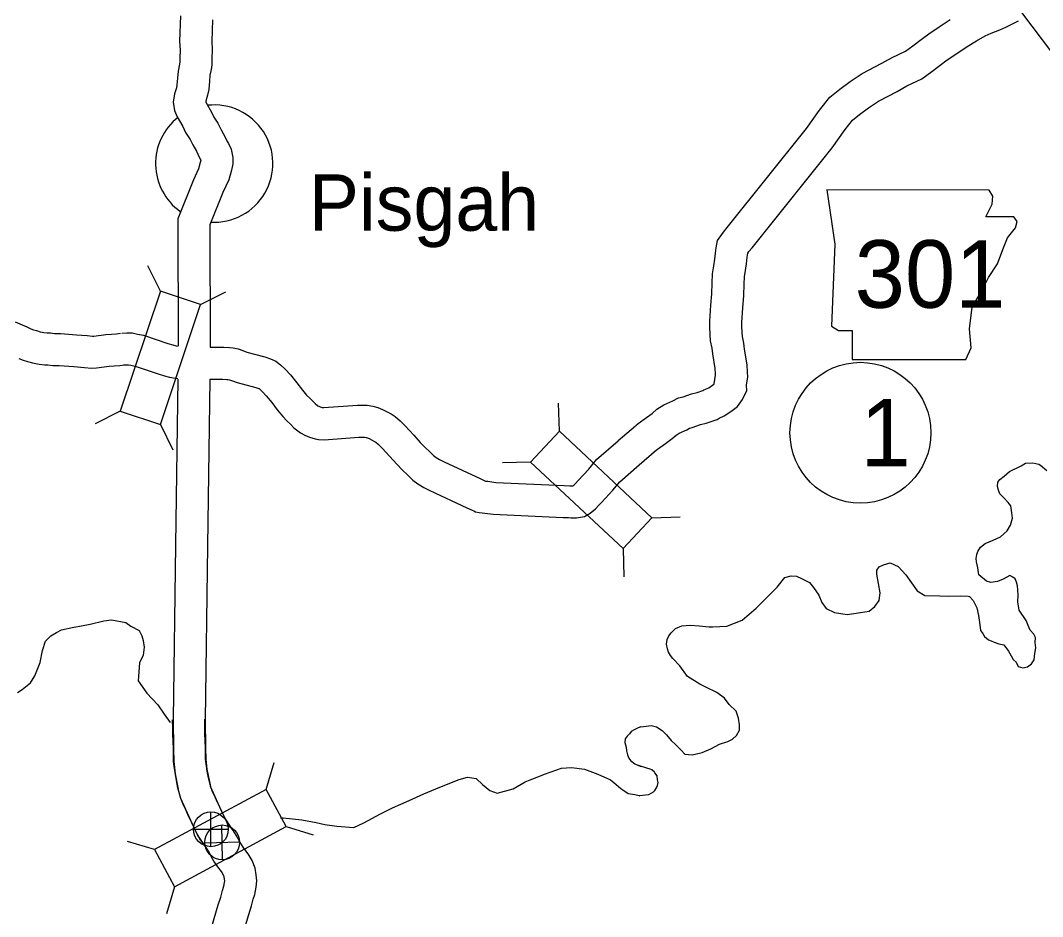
# Model space of a CAD drawing. Extents: x 79818 to 83933, y 50884 to 53307.
# Drawn here: x 81261.3 to 81389, y 52890.4 to 53002.4 of the extents above; entities that cross this region are included whole.
import ezdxf

# ---------------------------------------------------------------- set-up
doc = ezdxf.new("R2010")
doc.units = 0
for name, color, linetype in [('Level 10', 7, 'Continuous'), ('Level 2', 7, 'Continuous'), ('Level 20', 7, 'Continuous'), ('Level 21', 7, 'Continuous'), ('Level 24', 7, 'Continuous'), ('Level 26', 7, 'Continuous'), ('Level 27', 7, 'Continuous')]:
    doc.layers.add(name, color=color, linetype=linetype)

msp = doc.modelspace()

# ---------------------------------------------------------------- linework, layer by layer
at = {"layer": 'Level 10'}
for p, q in [((81280.69, 52936.77), (81280.4, 52915.03)), ((81284.69, 52936.72), (81284.4, 52914.97))]:
    msp.add_line(p, q, dxfattribs=at)
for points in [[(81281.3, 53002.94), (81281.19, 52999.77), (81281.24, 52998.67), (81281.22, 52997.72), (81281.21, 52997.21), (81281.16, 52996.92), (81281.01, 52996.03), (81280.93, 52995.16), (81280.86, 52994.33), (81280.78, 52993.95), (81280.57, 52993.2), (81280.37, 52992.15), (81280.53, 52991.13), (81280.89, 52990.33), (81281.6, 52989.11), (81281.94, 52988.35), (81282.49, 52987.51), (81282.85, 52986.81), (81283.28, 52986.02), (81283.61, 52985.3), (81283.81, 52984.99), (81283.82, 52984.97), (81283.83, 52984.92), (81283.77, 52984.6), (81283.56, 52983.84), (81282.91, 52982.46), (81280.96, 52977.57), (81280.99, 52961.71)], [(81285.29, 53002.47), (81285.2, 52999.79), (81285.24, 52998.72), (81285.22, 52997.63), (81285.2, 52996.83), (81285.11, 52996.26), (81284.98, 52995.52), (81284.92, 52994.79), (81284.82, 52993.75), (81284.67, 52993.03), (81284.47, 52992.28), (81284.45, 52992.17), (81284.45, 52992.16), (81285.17, 52990.93), (81285.47, 52990.27), (81285.95, 52989.53), (81286.38, 52988.69), (81286.87, 52987.8), (81287.13, 52987.23), (81287.29, 52986.98), (81287.63, 52986.29), (81287.85, 52985.25), (81287.82, 52984.46), (81287.66, 52983.67), (81287.32, 52982.45), (81286.59, 52980.87), (81284.96, 52976.81), (81284.99, 52961.54)], [(81338.19, 52951.76), (81338.46, 52951.98), (81339.51, 52952.73), (81340.21, 52953.26), (81340.81, 52953.77), (81341.66, 52954.32), (81342.78, 52954.81), (81343.49, 52955.19), (81344.1, 52955.33), (81345.11, 52955.69), (81345.83, 52955.86), (81346.54, 52956.12), (81346.69, 52956.21), (81347.29, 52956.47), (81347.75, 52956.77), (81347.94, 52956.92), (81347.96, 52956.95), (81348.14, 52958.04), (81348.13, 52958.19), (81348.09, 52958.87), (81347.78, 52960.7), (81347.7, 52961.39), (81347.51, 52962.32), (81347.45, 52963.13), (81347.4, 52964.06), (81347.42, 52964.8), (81347.54, 52966.77), (81347.68, 52968.21), (81347.7, 52969.52), (81347.74, 52970.7), (81347.9, 52971.71), (81348.03, 52972.55), (81348.14, 52973.3), (81348.21, 52973.96), (81348.37, 52974.87), (81349.14, 52975.93), (81349.6, 52976.49), (81359.49, 52988.86), (81361.12, 52991.17), (81362.4, 52992.77), (81363.66, 52993.77), (81364.94, 52994.73), (81366.45, 52995.73), (81368.89, 52997.03), (81370.21, 52997.76), (81371.86, 52998.53), (81372.77, 52999.21), (81373.81, 52999.99), (81374.76, 53000.7), (81376.07, 53001.58), (81377.43, 53002.48)], [(81340.7, 52948.65), (81340.88, 52948.8), (81341.88, 52949.5), (81342.71, 52950.13), (81343.2, 52950.55), (81343.57, 52950.79), (81344.53, 52951.21), (81344.89, 52951.41), (81345.21, 52951.48), (81346.24, 52951.85), (81346.97, 52952.02), (81348.34, 52952.51), (81348.6, 52952.68), (81349.2, 52952.94), (81350.03, 52953.49), (81350.88, 52954.11), (81351.48, 52955), (81352.04, 52956.1), (81351.99, 52956.8), (81352.16, 52957.84), (81352.12, 52958.43), (81352.07, 52959.33), (81351.74, 52961.27), (81351.65, 52962.03), (81351.48, 52962.86), (81351.45, 52963.39), (81351.41, 52964.11), (81351.42, 52964.63), (81351.53, 52966.46), (81351.68, 52967.98), (81351.7, 52969.42), (81351.73, 52970.32), (81351.86, 52971.1), (81351.99, 52971.97), (81352.1, 52972.79), (81352.16, 52973.29), (81352.3, 52973.48), (81352.7, 52973.96), (81362.69, 52986.45), (81364.32, 52988.76), (81365.25, 52989.92), (81366.11, 52990.61), (81367.25, 52991.46), (81368.5, 52992.29), (81370.8, 52993.51), (81372.03, 52994.2), (81373.91, 52995.08), (81375.17, 52996.01), (81376.2, 52996.79), (81377.07, 52997.43), (81378.29, 52998.26), (81379.58, 52999.1), (81380.75, 52999.83), (81381.82, 53000.45), (81382.55, 53000.8), (81383.65, 53001.21), (81384.4, 53001.54), (81385.96, 53002.32)], [(81260.66, 52964.72), (81262.09, 52964.06), (81262.6, 52963.84), (81262.94, 52963.71), (81263.3, 52963.6), (81263.76, 52963.47), (81264.03, 52963.41), (81264.22, 52963.37), (81264.65, 52963.33), (81265.04, 52963.31), (81265.58, 52963.26), (81266.33, 52963.24), (81268.3, 52963.09), (81269.66, 52962.99), (81270.29, 52962.92), (81270.47, 52962.93), (81271.96, 52963.11), (81272.69, 52963.18), (81273.32, 52963.22), (81273.8, 52963.29)], [(81273.99, 52963.3), (81274.61, 52963.33), (81275.26, 52963.32), (81275.92, 52963.18), (81276.68, 52963.02), (81279.71, 52962.01), (81280.36, 52961.81), (81280.75, 52961.71), (81280.99, 52961.67)], [(81284.99, 52961.52), (81286.22, 52961.53), (81286.72, 52961.52), (81287.4, 52961.49), (81287.86, 52961.44), (81288.49, 52961.31), (81289.1, 52961.1), (81289.57, 52960.93), (81291.85, 52960.32), (81292.53, 52960.09), (81293.21, 52959.79), (81293.79, 52959.33), (81294.37, 52958.8), (81295.04, 52958.06), (81295.83, 52957.09), (81296.52, 52956.17), (81297.04, 52955.55), (81297.44, 52955.14), (81297.85, 52954.73), (81298.1, 52954.48), (81298.47, 52954.2), (81298.56, 52954.15), (81298.75, 52954.06), (81298.99, 52953.99), (81299, 52953.99), (81299.22, 52953.98), (81303.41, 52954.29), (81303.77, 52954.29), (81304.08, 52954.3), (81304.61, 52954.27), (81305.33, 52954.18), (81305.95, 52954), (81306.52, 52953.75), (81307.05, 52953.49), (81307.62, 52953.19), (81308.11, 52952.86), (81308.72, 52952.34), (81309.38, 52951.69), (81310.43, 52950.54), (81311.23, 52949.63), (81311.89, 52948.96), (81312.35, 52948.52), (81312.91, 52948), (81313.22, 52947.76), (81313.67, 52947.48), (81314.23, 52947.19), (81318.72, 52945.1), (81319.33, 52944.82), (81319.4, 52944.79), (81319.44, 52944.79), (81319.7, 52944.77), (81320.7, 52944.64), (81329.21, 52944.24), (81329.95, 52944.22), (81330.23, 52944.2), (81330.32, 52944.2), (81330.42, 52944.28), (81330.63, 52944.51), (81330.99, 52944.89), (81332.3, 52946.29), (81333.26, 52947.48), (81335.96, 52949.84)], [(81261.09, 52960.13), (81261.64, 52959.93), (81262.17, 52959.76), (81262.8, 52959.59), (81263.21, 52959.5), (81263.63, 52959.41), (81264.35, 52959.34), (81264.74, 52959.32), (81265.35, 52959.26), (81266.13, 52959.25), (81267.99, 52959.1), (81269.3, 52959), (81270.18, 52958.91), (81270.82, 52958.94), (81272.4, 52959.14), (81273, 52959.2), (81273.71, 52959.24), (81274.35, 52959.32)], [(81274.16, 52959.31), (81274.66, 52959.33), (81274.81, 52959.33), (81275.1, 52959.27), (81275.63, 52959.16), (81278.51, 52958.19), (81279.31, 52957.95), (81279.91, 52957.8), (81280.62, 52957.67), (81280.97, 52957.62)], [(81280.96, 52957.55), (81280.69, 52936.84), (81280.68, 52936.77)], [(81284.96, 52957.5), (81284.69, 52936.72)], [(81284.96, 52957.52), (81286.21, 52957.53), (81286.59, 52957.52), (81287.07, 52957.5), (81287.23, 52957.48), (81287.43, 52957.44), (81287.78, 52957.32), (81288.38, 52957.11), (81290.7, 52956.48), (81291.09, 52956.36), (81291.11, 52956.35), (81291.19, 52956.29), (81291.53, 52955.97), (81292.01, 52955.45), (81292.69, 52954.62), (81293.38, 52953.69), (81294.07, 52952.87), (81294.59, 52952.33), (81295.02, 52951.9), (81295.45, 52951.47), (81296.28, 52950.83), (81296.81, 52950.54), (81297.4, 52950.29), (81298.1, 52950.08), (81298.55, 52950.01), (81299.23, 52949.97), (81303.59, 52950.29), (81303.84, 52950.29), (81304.02, 52950.3), (81304.27, 52950.28), (81304.51, 52950.26), (81304.55, 52950.24), (81304.85, 52950.11), (81305.26, 52949.92), (81305.55, 52949.76), (81305.69, 52949.67), (81306.01, 52949.4), (81306.49, 52948.92), (81307.45, 52947.86), (81308.31, 52946.9), (81309.09, 52946.1), (81309.61, 52945.61), (81310.33, 52944.93), (81310.96, 52944.46), (81311.68, 52944.01), (81312.46, 52943.6), (81317.05, 52941.47), (81317.73, 52941.15), (81317.93, 52941.07), (81318.15, 52940.96), (81318.62, 52940.86), (81318.99, 52940.81), (81319.3, 52940.78), (81320.36, 52940.65), (81329.08, 52940.24), (81329.76, 52940.23), (81330.05, 52940.2), (81330.75, 52940.2), (81331.77, 52940.39), (81332.47, 52940.8), (81333.15, 52941.34), (81333.56, 52941.79), (81333.91, 52942.16), (81335.31, 52943.66), (81336.16, 52944.7), (81338.59, 52946.83)], [(81335.97, 52949.85), (81338.14, 52951.72)], [(81338.58, 52946.82), (81340.75, 52948.69)], [(81285.21, 52889.14), (81286.02, 52891.82), (81286.32, 52892.78), (81286.53, 52893.63), (81286.71, 52894.18), (81286.81, 52894.61), (81286.82, 52894.82), (81286.8, 52895.04), (81286.75, 52895.31), (81286.63, 52895.64), (81286.42, 52895.98), (81285.96, 52896.6), (81285.48, 52897.3), (81285.12, 52897.89), (81284.86, 52898.4), (81284.57, 52898.89), (81284.25, 52899.34), (81283.73, 52900.08), (81283.42, 52900.61), (81283, 52901.46), (81282.7, 52902.09), (81282.31, 52902.93), (81282, 52903.6), (81281.69, 52904.27), (81281.33, 52905.12), (81281.13, 52905.88), (81280.98, 52906.45), (81280.83, 52907.12), (81280.7, 52907.87), (81280.54, 52908.89), (81280.43, 52909.74), (81280.41, 52911.32), (81280.34, 52913.22), (81280.33, 52913.91), (81280.32, 52914.97)], [(81280.4, 52915), (81280.41, 52911.32), (81280.48, 52909.74), (81280.62, 52908.21), (81281.02, 52906.3)], [(81289, 52887.87), (81289.84, 52890.64), (81290.17, 52891.69), (81290.38, 52892.53), (81290.58, 52893.14), (81290.77, 52894.04), (81290.83, 52894.84), (81290.77, 52895.6), (81290.61, 52896.42), (81290.24, 52897.38), (81289.75, 52898.2), (81289.22, 52898.92), (81288.84, 52899.48), (81288.61, 52899.85), (81288.36, 52900.33), (81287.93, 52901.07), (81287.52, 52901.64), (81287.1, 52902.25), (81286.93, 52902.53), (81286.6, 52903.2), (81286.33, 52903.78), (81285.94, 52904.61), (81285.63, 52905.28), (81285.35, 52905.89), (81285.12, 52906.43), (81285, 52906.89), (81284.87, 52907.38), (81284.75, 52907.91), (81284.64, 52908.53), (81284.5, 52909.46), (81284.42, 52910.03), (81284.41, 52911.42), (81284.34, 52913.3), (81284.33, 52913.95), (81284.32, 52915.03)], [(81284.4, 52915), (81284.41, 52911.42), (81284.47, 52910.02), (81284.59, 52908.8), (81285.04, 52906.62)], [(81284.63, 52898.77), (81284.56, 52898.9), (81284.24, 52899.36), (81283.43, 52900.57), (81282.99, 52901.47), (81281.33, 52905.1), (81281.02, 52906.3)], [(81288.1, 52900.76), (81287.93, 52901.06), (81287.53, 52901.62), (81286.91, 52902.56), (81286.6, 52903.19), (81285.04, 52906.62)]]:
    msp.add_lwpolyline(points, dxfattribs=at)
at = {"layer": 'Level 2'}
for points in [[(81388.13, 52923.95), (81388.06, 52924.6), (81388.08, 52925.26), (81387.9, 52925.66), (81387.42, 52926.16), (81387.18, 52926.75), (81386.94, 52927.39), (81386.06, 52928.68), (81385.88, 52929.72), (81385.93, 52930.55), (81385.91, 52931.22), (81385.87, 52931.71), (81385.74, 52932.17), (81385.57, 52932.56), (81385.27, 52932.79), (81384.9, 52932.99), (81384.07, 52932.52), (81383.34, 52932.23), (81382.53, 52932.14), (81381.97, 52932.27), (81381.04, 52933.08), (81380.88, 52933.96), (81380.71, 52934.7), (81380.7, 52935.12), (81380.76, 52935.64), (81380.88, 52936), (81381.25, 52936.52), (81381.8, 52936.98), (81382.81, 52937.43), (81383.74, 52937.81), (81384.58, 52938.56), (81384.96, 52939.28), (81385.24, 52940.17), (81385.14, 52940.83), (81385, 52941.7), (81384.68, 52942.13), (81384.13, 52942.71), (81383.66, 52943.22), (81383.46, 52943.68), (81383.37, 52944.12), (81383.4, 52944.65), (81383.65, 52945), (81384.19, 52945.42), (81384.86, 52945.99), (81386.29, 52946.7), (81386.83, 52947.03), (81387.76, 52947.08), (81388.52, 52946.9), (81388.74, 52946.79), (81389.52, 52946.11)], [(81338.82, 52914.09), (81340.1, 52914.24), (81340.76, 52914.08), (81341.48, 52913.6), (81342.01, 52913.09), (81342.57, 52912.39), (81343.13, 52911.88), (81343.82, 52911.18), (81344.29, 52910.67), (81345.21, 52910.59), (81345.76, 52910.69), (81346.47, 52910.87), (81347.55, 52911.32), (81348.62, 52911.9), (81349.68, 52912.25), (81350.25, 52912.52), (81350.77, 52913), (81351.12, 52913.65), (81351.12, 52914.32), (81351.01, 52915.16), (81350.69, 52916.03), (81349.83, 52916.88), (81349.27, 52917.67), (81348.28, 52918.35), (81346.94, 52919.02), (81346.19, 52919.41), (81344.63, 52920.39), (81343.67, 52921.69), (81342.79, 52922.62), (81342.49, 52922.98), (81342.27, 52923.4), (81342.13, 52923.84), (81342.02, 52924.4), (81342.1, 52924.99), (81342.29, 52925.46), (81342.57, 52925.81), (81343.15, 52926.36), (81343.94, 52926.71), (81344.96, 52926.78), (81346.08, 52926.72), (81347.34, 52926.56), (81347.8, 52926.58), (81349.54, 52926.65), (81351.44, 52927.41), (81353.21, 52928.91), (81354.23, 52929.96), (81355.82, 52931.54), (81356.79, 52932.73), (81357.6, 52932.95), (81358.23, 52932.92), (81358.85, 52932.63), (81359.89, 52932.14), (81360.35, 52931.5), (81361.05, 52930.55), (81361.43, 52929.6), (81361.97, 52928.88), (81362.98, 52928.36), (81364.58, 52928.11), (81366.24, 52928.36), (81367.33, 52928.55), (81368.01, 52929.1), (81368.56, 52929.85), (81368.71, 52930.82), (81368.48, 52932.01), (81368.29, 52933.16), (81368.26, 52933.68), (81368.56, 52934.06), (81369.11, 52934.34), (81369.94, 52934.56), (81370.93, 52934.13), (81371.91, 52933.09), (81373.31, 52931.06), (81374.29, 52930.49), (81376.17, 52930.46), (81377.19, 52930.4), (81378.76, 52930.45), (81379.67, 52930.43), (81379.87, 52930.35), (81380.31, 52929.88), (81380.76, 52928.94), (81380.96, 52928), (81381.14, 52926.84), (81381.24, 52926.13), (81381.53, 52925.75), (81381.72, 52925.37), (81382.21, 52924.97), (81382.56, 52924.84), (81382.93, 52924.66), (81383.54, 52924.44), (81384.16, 52924.32), (81384.71, 52923.52), (81385.06, 52922.95), (81385.33, 52922.5), (81385.68, 52922.17), (81385.93, 52921.64), (81386.53, 52921.44), (81387.09, 52921.57), (81387.6, 52921.97), (81387.93, 52922.45), (81388.03, 52923.23), (81388.13, 52923.95)], [(81260.94, 52918.38), (81261.54, 52918.74), (81262.56, 52919.59), (81263.09, 52920.45), (81263.75, 52922.1), (81264.06, 52923.63), (81264.44, 52924.79), (81265.11, 52925.47), (81265.81, 52925.85), (81266.43, 52926.21), (81267.99, 52926.55), (81268.94, 52926.69), (81270, 52926.93), (81271.74, 52927.31), (81272.7, 52927.45), (81274.45, 52927.13), (81275.11, 52926.65), (81276.12, 52926.12), (81276.47, 52925.47), (81276.64, 52924.85), (81276.75, 52924.05), (81276.64, 52923.03), (81276.17, 52922.09), (81276.02, 52919.81), (81277.1, 52918.3), (81278.46, 52916.84), (81279.24, 52915.66), (81279.99, 52914.6)], [(81338.82, 52914.09), (81338.45, 52913.94), (81337.95, 52913.69), (81337.61, 52913.48), (81337.4, 52913.22), (81337.1, 52912.92), (81336.85, 52912.59), (81336.82, 52912.1), (81336.95, 52911.54), (81337, 52911.06), (81337.13, 52910.56), (81337.31, 52910.17), (81337.52, 52909.89), (81338.04, 52909.46), (81338.52, 52909.24), (81338.84, 52909.14)], [(81293.81, 52902.71), (81294.11, 52902.7), (81296.44, 52902.44), (81298.26, 52902.14), (81299.33, 52901.88), (81300.83, 52901.65), (81302.96, 52901.49), (81304.2, 52902.06), (81306.3, 52903.2), (81307.76, 52903.94), (81309.87, 52904.85), (81311.7, 52905.7), (81313.21, 52906.32), (81315.14, 52907.1), (81316.12, 52907.48), (81317.13, 52907.8), (81318.22, 52907.61), (81319.03, 52906.89), (81319.93, 52906.14), (81320.86, 52905.8), (81322.84, 52906.33), (81324.37, 52907.19), (81324.96, 52907.44), (81326.07, 52907.88), (81326.76, 52908.17), (81328.9, 52908.93), (81330.14, 52909.01), (81331.76, 52908.78), (81333.41, 52908.15), (81335, 52907.46), (81335.41, 52907.11)], [(81338.61, 52905.48), (81339.82, 52905.63), (81340.39, 52905.97), (81340.55, 52906.12), (81340.74, 52906.45), (81340.87, 52906.76), (81340.96, 52907.12), (81340.9, 52907.45), (81340.86, 52907.94), (81340.57, 52908.31), (81340.51, 52908.4), (81340.18, 52908.71), (81339.97, 52908.77), (81339.57, 52908.9), (81338.52, 52909.24)], [(81335.41, 52907.11), (81336.3, 52906.35), (81336.8, 52906.02), (81337.22, 52905.76), (81338.06, 52905.61), (81338.61, 52905.48), (81338.69, 52905.46)]]:
    msp.add_lwpolyline(points, dxfattribs=at)
at = {"layer": 'Level 20'}
for p, q in [((81278.8, 52968.55), (81277.23, 52971.7)), ((81283.81, 52966.88), (81286.96, 52968.44)), ((81273.77, 52953.53), (81270.62, 52951.97)), ((81328.63, 52951.04), (81328.52, 52954.55)), ((81278.78, 52951.86), (81280.34, 52948.71)), ((81325.02, 52947.18), (81321.51, 52947.07)), ((81340.19, 52940.2), (81343.71, 52940.32)), ((81336.58, 52936.35), (81336.69, 52932.83)), ((81292.01, 52906.25), (81293.01, 52909.62)), ((81292.01, 52906.25), (81293.01, 52909.62)), ((81294.51, 52901.61), (81297.89, 52900.6)), ((81294.51, 52901.61), (81297.89, 52900.6)), ((81278.07, 52898.73), (81274.69, 52899.74)), ((81278.07, 52898.73), (81274.69, 52899.74)), ((81280.57, 52894.08), (81279.57, 52890.71)), ((81280.57, 52894.08), (81279.57, 52890.71))]:
    msp.add_line(p, q, dxfattribs=at)
for points in [[(81394.56, 53001.23), (81385.06, 53013.91), (81380.83, 53010.74), (81390.34, 52998.06)], [(81278.78, 52951.86), (81283.81, 52966.88), (81278.8, 52968.55), (81273.77, 52953.53)], [(81325.02, 52947.18), (81336.58, 52936.35), (81340.19, 52940.2), (81328.63, 52951.04)], [(81292.01, 52906.25), (81278.07, 52898.73), (81280.57, 52894.08), (81294.51, 52901.61)], [(81292.01, 52906.25), (81278.07, 52898.73), (81280.57, 52894.08), (81294.51, 52901.61)]]:
    msp.add_lwpolyline(points, close=True, dxfattribs=at)
at = {"layer": 'Level 21'}
msp.add_lwpolyline([(81362.03, 52981.19), (81363.05, 52974.43), (81362.6, 52964.16), (81363.5, 52963.6), (81365.19, 52963.6), (81365.19, 52959.99), (81379.4, 52959.99), (81380.08, 52961.45), (81379.85, 52963.82), (81380.19, 52966.53), (81381.43, 52968.67), (81382.22, 52970.25), (81383.35, 52971.94), (81384.03, 52973.75), (81384.59, 52975.21), (81385.61, 52976.46), (81385.83, 52977.24), (81385.38, 52977.81), (81381.88, 52977.81), (81382.67, 52979.39), (81382.79, 52980.4), (81382.32, 52981.18)], close=True, dxfattribs=at)
at = {"layer": 'Level 24'}
for start, end in [(266.5318, 96.4044), (128.0273, 234.5301)]:
    msp.add_arc((81285.51, 52984.48), 7.33, start, end, dxfattribs=at)
at = {"layer": 'Level 26'}
for p, q in [((81285.1, 52899.1), (81285.1, 52903.43)), ((81282.93, 52901.27), (81287.27, 52901.27)), ((81286.56, 52897.47), (81286.46, 52901.81)), ((81284.34, 52899.59), (81288.68, 52899.69))]:
    msp.add_line(p, q, dxfattribs=at)
for centre in [(81285.1, 52901.27), (81286.51, 52899.64)]:
    msp.add_circle(centre, 2.17, dxfattribs=at)
at = {"layer": 'Level 27'}
msp.add_circle((81366.23, 52950.84), 8.8, dxfattribs=at)

# ---------------------------------------------------------------- texts
at = {"layer": 'Level 21'}
msp.add_text('301', height=8.448, dxfattribs=at).set_placement((81365.51, 52966.46))
at = {"layer": 'Level 24'}
msp.add_text('Pisgah', height=7.04, dxfattribs=at).set_placement((81297.31, 52976.09))
at = {"layer": 'Level 27'}
msp.add_text('1', height=8.45, dxfattribs=at).set_placement((81366.23, 52946.62))

doc.saveas('drawing.dxf')
